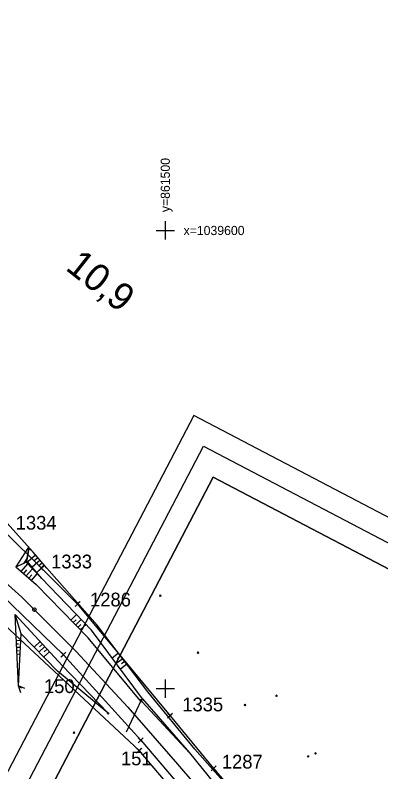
# Model space of a CAD drawing. Extents: x -866402 to -860377, y -1041908 to -1038598.
# Drawn here: x -861532.8 to -861452.9, y -1039718.2 to -1039553 of the extents above; entities that cross this region are included whole.
import ezdxf

# ---------------------------------------------------------------- set-up
doc = ezdxf.new("R2010")
doc.units = 0
for name, color, linetype in [('PS 02 trasa', 7, 'Continuous'), ('SZDC', 7, 'Continuous'), ('Vrstva 1', 7, 'Continuous'), ('Vrstva 16', 7, 'Continuous'), ('Vrstva 17', 7, 'Continuous'), ('Vrstva 19', 7, 'Continuous'), ('Vrstva 48', 7, 'Continuous'), ('Vrstva 49', 7, 'Continuous'), ('Vrstva 5', 7, 'Continuous'), ('Vrstva 60', 7, 'Continuous'), ('Vrstva 7', 7, 'Continuous')]:
    doc.layers.add(name, color=color, linetype=linetype)

msp = doc.modelspace()

# ---------------------------------------------------------------- linework, layer by layer
at = {"layer": 'PS 02 trasa'}
msp.add_lwpolyline([(-861734.94, -1039565.48), (-861714.17, -1039579.85), (-861692.5, -1039591.72), (-861679.17, -1039597.93), (-861669.42, -1039602.48), (-861646.49, -1039612.82), (-861623.81, -1039623.04), (-861599.73, -1039634.4), (-861591.94, -1039638.84), (-861559.23, -1039660.24), (-861540.24, -1039675.31), (-861522.22, -1039692.58), (-861505.35, -1039711.25), (-861489.08, -1039730.28), (-861472.81, -1039749.33), (-861456.55, -1039768.41), (-861440.35, -1039787.41)], dxfattribs=at)
at = {"layer": 'SZDC'}
for points in [[(-861729.85, -1039553), (-861707.85, -1039572.19), (-861683.49, -1039587.43), (-861648.26, -1039601.57), (-861584.91, -1039634.69), (-861543.49, -1039657.42), (-861534.95, -1039665.88), (-861527.09, -1039673.66), (-861519.15, -1039681.53), (-861498.94, -1039705.92), (-861489.43, -1039717.4), (-861392.94, -1039828.48), (-861296.45, -1039939.55), (-861273.55, -1039965.91), (-861261.75, -1039976.4), (-861207.66, -1040016.44)], [(-861236.71, -1040010.09), (-861295.08, -1039961.46), (-861327.14, -1039923.72), (-861355.62, -1039890.18), (-861362.07, -1039906.25), (-861375.91, -1039876.55), (-861379.94, -1039865.44), (-861377.18, -1039864.81), (-861381.07, -1039860.23), (-861505.7, -1039713.51), (-861552.61, -1039669.88), (-861558.17, -1039663.76), (-861561.3, -1039661.32), (-861593.45, -1039638.2), (-861610.89, -1039630.24), (-861649.01, -1039618.14), (-861669.39, -1039610.88), (-861739.98, -1039582.51)]]:
    msp.add_lwpolyline(points, dxfattribs=at)
at = {"layer": 'Vrstva 1'}
msp.add_lwpolyline([(-861629.98, -1039617.19), (-861614.37, -1039624.37), (-861599.2, -1039631.91), (-861584.31, -1039640.17), (-861569.86, -1039649.29), (-861556.31, -1039658.9), (-861544.58, -1039668.2), (-861531.3, -1039680.04), (-861519.43, -1039691.88), (-861508.19, -1039704.07), (-861497.3, -1039716.49), (-861486.21, -1039729.46)], dxfattribs=at)
for points in [[(-861631.44, -1039903.51), (-860515.05, -1040487.66), (-860377.36, -1040224.52), (-861493.75, -1039640.37)], [(-861491.64, -1039647.11), (-860384.11, -1040226.63), (-860517.16, -1040480.91), (-861624.69, -1039901.4)], [(-861617.95, -1039899.29), (-860700.91, -1040379.13), (-860572.48, -1040133.7), (-861489.53, -1039653.85)], [(-861489.53, -1039653.85), (-860572.48, -1040133.7), (-860700.91, -1040379.13), (-861617.95, -1039899.29)]]:
    msp.add_lwpolyline(points, close=True, dxfattribs=at)
msp.add_circle((-861528.59, -1039682.75), 0.4, dxfattribs=at)
at = {"layer": 'Vrstva 16'}
msp.add_lwpolyline([(-861532.62, -1039673.39), (-861530.82, -1039672.6), (-861530.13, -1039671.58), (-861529.8, -1039669.36), (-861529.99, -1039669.33), (-861532.62, -1039673.39)], dxfattribs=at)
at = {"layer": 'Vrstva 17'}
for points in [[(-861493.56, -1039713.17), (-861503.83, -1039700.67), (-861514.86, -1039686.11), (-861525.84, -1039673.7), (-861528.85, -1039670.22), (-861536.51, -1039661.75), (-861550.27, -1039649.73), (-861562.48, -1039642.97), (-861580.09, -1039633.69), (-861593.79, -1039624.09)], [(-861316.51, -1039917.26), (-861344.58, -1039884.97), (-861370.45, -1039854.39), (-861399.86, -1039822.88), (-861428.34, -1039789.46), (-861456.44, -1039756.08), (-861482.37, -1039725.82), (-861493.56, -1039713.17)]]:
    msp.add_lwpolyline(points, dxfattribs=at)
at = {"layer": 'Vrstva 19'}
msp.add_line((-861508.49, -1039709.43), (-861505.17, -1039702.46), dxfattribs=at)
for points in [[(-861530.82, -1039672.6), (-861530.13, -1039671.58), (-861530.31, -1039672), (-861530.49, -1039672.26), (-861530.82, -1039672.6)], [(-861505.51, -1039702.6), (-861505.07, -1039702.84), (-861505.01, -1039702.67), (-861505.46, -1039702.43), (-861505.51, -1039702.6)], [(-861505.01, -1039702.67), (-861505.17, -1039702.46), (-861505.46, -1039702.43)]]:
    msp.add_lwpolyline(points, dxfattribs=at)
at = {"layer": 'Vrstva 48'}
for p, q in [((-861528.31, -1039670.85), (-861530.02, -1039672.34)), ((-861527.32, -1039671.99), (-861529.04, -1039673.48)), ((-861527.81, -1039671.42), (-861528.67, -1039672.17)), ((-861526.83, -1039672.56), (-861527.69, -1039673.3)), ((-861531.47, -1039674.4), (-861530.03, -1039672.74)), ((-861530.91, -1039674.89), (-861530.21, -1039674.09)), ((-861530.35, -1039675.39), (-861528.98, -1039673.83)), ((-861526.34, -1039673.12), (-861528.07, -1039674.62)), ((-861529.78, -1039675.88), (-861529.12, -1039675.12)), ((-861529.22, -1039676.38), (-861527.94, -1039674.91)), ((-861520.64, -1039685.04), (-861519.37, -1039683.8)), ((-861520.12, -1039685.57), (-861519.49, -1039684.96)), ((-861519.6, -1039686.11), (-861518.33, -1039684.88)), ((-861519.08, -1039686.65), (-861518.44, -1039686.03)), ((-861518.55, -1039687.19), (-861517.29, -1039685.96)), ((-861532.51, -1039689.46), (-861531.56, -1039689.41)), ((-861532.47, -1039690.21), (-861532.03, -1039690.19)), ((-861527.32, -1039689.72), (-861528.63, -1039690.94)), ((-861526.81, -1039690.28), (-861527.46, -1039690.88)), ((-861532.44, -1039690.96), (-861531.63, -1039690.92)), ((-861532.4, -1039691.71), (-861532.03, -1039691.69)), ((-861526.3, -1039690.83), (-861527.58, -1039692.01)), ((-861525.28, -1039691.93), (-861526.54, -1039693.08)), ((-861525.79, -1039691.38), (-861526.43, -1039691.96)), ((-861510.2, -1039692.27), (-861511.58, -1039693.31)), ((-861532.37, -1039692.46), (-861531.7, -1039692.42)), ((-861509.29, -1039693.46), (-861510.69, -1039694.52)), ((-861509.74, -1039692.86), (-861510.44, -1039693.39)), ((-861508.84, -1039694.06), (-861509.54, -1039694.59)), ((-861508.39, -1039694.66), (-861509.79, -1039695.72))]:
    msp.add_line(p, q, dxfattribs=at)
at = {"layer": 'Vrstva 49'}
for p, q in [((-861528.85, -1039670.22), (-861529.8, -1039669.36)), ((-861525.84, -1039673.7), (-861528.85, -1039670.22)), ((-861530.49, -1039672.26), (-861526.92, -1039675.96)), ((-861526.92, -1039675.96), (-861530.31, -1039672)), ((-861525.84, -1039673.7), (-861514.86, -1039686.11)), ((-861501.25, -1039679.53), (-861500.9, -1039679.88)), ((-861501.25, -1039679.88), (-861500.9, -1039679.53)), ((-861531.49, -1039688.02), (-861532.79, -1039683.8)), ((-861532.03, -1039699.41), (-861532.79, -1039683.8)), ((-861532.03, -1039699.41), (-861531.49, -1039688.02)), ((-861493.01, -1039691.96), (-861492.66, -1039692.31)), ((-861493.01, -1039692.31), (-861492.66, -1039691.96)), ((-861531.55, -1039700.89), (-861532.03, -1039699.41)), ((-861530.68, -1039699.94), (-861532.03, -1039699.41)), ((-861531.37, -1039699.88), (-861532.03, -1039699.41)), ((-861505.17, -1039702.46), (-861504.97, -1039702.25)), ((-861504.97, -1039702.25), (-861494.71, -1039714.01)), ((-861475.88, -1039701.33), (-861475.53, -1039701.68)), ((-861475.88, -1039701.68), (-861475.53, -1039701.33)), ((-861482.77, -1039703.41), (-861482.41, -1039703.76)), ((-861482.77, -1039703.76), (-861482.41, -1039703.41)), ((-861512.65, -1039705.18), (-861512.3, -1039705.53)), ((-861512.65, -1039705.53), (-861512.3, -1039705.18)), ((-861520.12, -1039709.4), (-861519.77, -1039709.75)), ((-861520.12, -1039709.75), (-861519.77, -1039709.4)), ((-861468.96, -1039714.58), (-861468.61, -1039714.93)), ((-861468.96, -1039714.93), (-861468.61, -1039714.58)), ((-861467.37, -1039713.94), (-861467.02, -1039714.29)), ((-861467.37, -1039714.29), (-861467.02, -1039713.94))]:
    msp.add_line(p, q, dxfattribs=at)
for points in [[(-861529.8, -1039669.36), (-861530.13, -1039671.58), (-861530.31, -1039672)], [(-861532.62, -1039673.39), (-861530.82, -1039672.6), (-861530.49, -1039672.26)], [(-861532.62, -1039673.39), (-861528.2, -1039677.27), (-861516.86, -1039688.93)], [(-861504.97, -1039702.25), (-861516.08, -1039687.22), (-861526.92, -1039675.96)], [(-861512.47, -1039705.35), (-861522.51, -1039694.93), (-861532.79, -1039683.8)], [(-861493.56, -1039713.17), (-861503.83, -1039700.67), (-861514.86, -1039686.11)], [(-861512.47, -1039705.35), (-861523.54, -1039696.15), (-861531.49, -1039688.02)], [(-861505.17, -1039702.46), (-861505.46, -1039702.43), (-861505.51, -1039702.6), (-861516.86, -1039688.93)], [(-861494.71, -1039714.01), (-861505.07, -1039702.84), (-861505.01, -1039702.67), (-861505.17, -1039702.46)], [(-861370.45, -1039854.39), (-861399.86, -1039822.88), (-861428.34, -1039789.46), (-861456.44, -1039756.08), (-861482.37, -1039725.82), (-861493.56, -1039713.17)], [(-861494.71, -1039714.01), (-861483.92, -1039727.3), (-861458.07, -1039757.64), (-861430.16, -1039790.88), (-861401.04, -1039823.61), (-861371.75, -1039855.75)]]:
    msp.add_lwpolyline(points, dxfattribs=at)
at = {"layer": 'Vrstva 5'}
for p, q in [((-861500, -1039598), (-861500, -1039602)), ((-861502, -1039600), (-861498, -1039600)), ((-861500, -1039698), (-861500, -1039702)), ((-861502, -1039700), (-861498, -1039700))]:
    msp.add_line(p, q, dxfattribs=at)
at = {"layer": 'Vrstva 60'}
for p, q in [((-861526.64, -1039674.11), (-861527.64, -1039673.11)), ((-861526.64, -1039673.21), (-861527.64, -1039674.21)), ((-861527.54, -1039674.11), (-861526.54, -1039673.11)), ((-861527.54, -1039673.21), (-861526.54, -1039674.21)), ((-861527.09, -1039673.66), (-861527.09, -1039673.66)), ((-861518.7, -1039681.98), (-861519.7, -1039680.98)), ((-861518.7, -1039681.08), (-861519.7, -1039682.08)), ((-861519.6, -1039681.98), (-861518.6, -1039680.98)), ((-861519.6, -1039681.08), (-861518.6, -1039682.08)), ((-861519.15, -1039681.53), (-861519.15, -1039681.53)), ((-861521.78, -1039693.03), (-861522.78, -1039692.03)), ((-861521.78, -1039692.13), (-861522.78, -1039693.13)), ((-861522.68, -1039693.03), (-861521.68, -1039692.03)), ((-861522.68, -1039692.13), (-861521.68, -1039693.13)), ((-861522.22, -1039692.58), (-861522.22, -1039692.58)), ((-861498.49, -1039706.37), (-861499.49, -1039705.37)), ((-861498.49, -1039705.47), (-861499.49, -1039706.47)), ((-861499.39, -1039706.37), (-861498.39, -1039705.37)), ((-861499.39, -1039705.47), (-861498.39, -1039706.47)), ((-861498.94, -1039705.92), (-861498.94, -1039705.92)), ((-861504.9, -1039711.7), (-861505.9, -1039710.7)), ((-861504.9, -1039710.8), (-861505.9, -1039711.8)), ((-861505.8, -1039711.7), (-861504.8, -1039710.7)), ((-861505.8, -1039710.8), (-861504.8, -1039711.8)), ((-861505.35, -1039711.25), (-861505.35, -1039711.25)), ((-861505.25, -1039713.96), (-861506.25, -1039712.96)), ((-861505.25, -1039713.06), (-861506.25, -1039714.06)), ((-861506.15, -1039713.96), (-861505.15, -1039712.96)), ((-861506.15, -1039713.06), (-861505.15, -1039714.06)), ((-861505.7, -1039713.51), (-861505.7, -1039713.51)), ((-861488.98, -1039717.85), (-861489.98, -1039716.85)), ((-861488.98, -1039716.95), (-861489.98, -1039717.95)), ((-861489.88, -1039717.85), (-861488.88, -1039716.85)), ((-861489.88, -1039716.95), (-861488.88, -1039717.95)), ((-861489.43, -1039717.4), (-861489.43, -1039717.4))]:
    msp.add_line(p, q, dxfattribs=at)

# ---------------------------------------------------------------- texts
at = {"layer": 'Vrstva 5'}
msp.add_text('y=861500', height=2, rotation=90, dxfattribs=at).set_placement((-861499, -1039596))
msp.add_text('x=1039600', height=2, dxfattribs=at).set_placement((-861496, -1039601))
at = {"layer": 'Vrstva 60'}
for s, p in [('1334', (-861532.66, -1039665.29)), ('1333', (-861524.92, -1039673.75)), ('1286', (-861516.43, -1039682.05)), ('150', (-861526.49, -1039700.96)), ('1335', (-861496.28, -1039704.95)), ('151', (-861509.68, -1039716.73)), ('1287', (-861487.64, -1039717.43))]:
    msp.add_text(s, height=3, dxfattribs=at).set_placement(p)
at = {"layer": 'Vrstva 7'}
msp.add_text('10,9', height=6, rotation=321.5949, dxfattribs=at).set_placement((-861522.01, -1039608.43))

doc.saveas('drawing.dxf')
